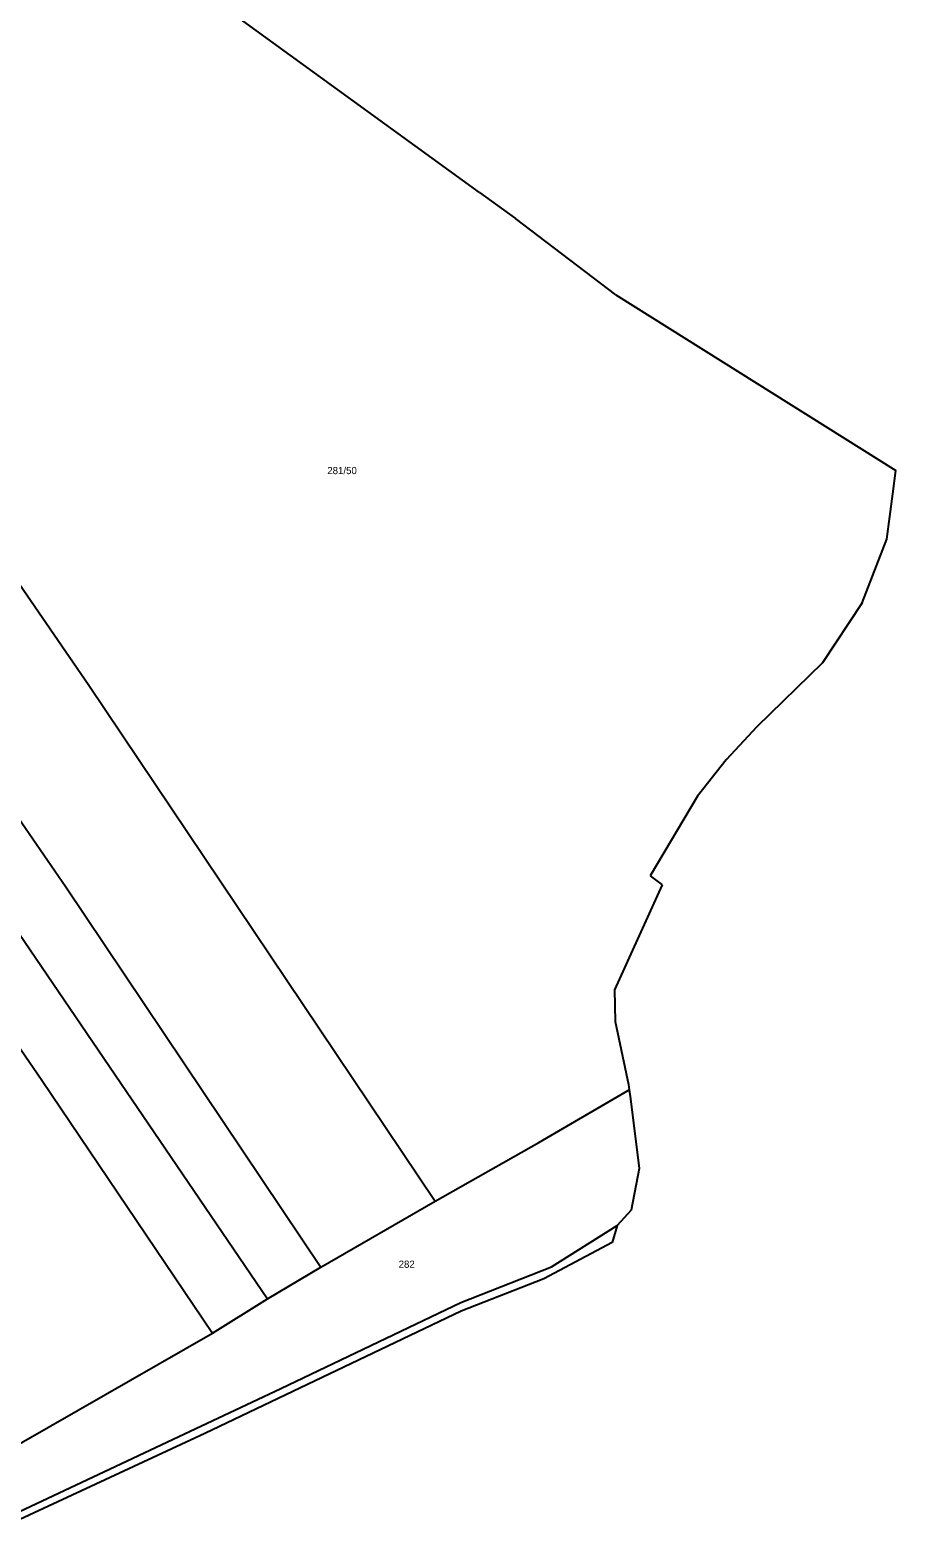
# Model space of a CAD drawing. Extents: x -779723 to -777378, y -1011169 to -1009297.
# Drawn here: x -777582.1 to -777378.3, y -1010780.6 to -1010425.5 of the extents above; entities that cross this region are included whole.
import ezdxf

# ---------------------------------------------------------------- set-up
doc = ezdxf.new("R2010")
doc.units = 0
doc.layers.add('KN_HRANICE', color=7, linetype='Continuous')
doc.layers.add('KN_PARCELY', color=7, linetype='Continuous')

msp = doc.modelspace()

# ---------------------------------------------------------------- linework, layer by layer
at = {"layer": 'KN_HRANICE'}
for p, q in [((-777476.3, -1010463.75), (-777554.28, -1010407.13)), ((-777673.1, -1010427.53), (-777568.32, -1010579.76)), ((-777476.3, -1010463.75), (-777467.85, -1010469.89)), ((-777444.27, -1010487.85), (-777467.85, -1010469.89)), ((-777444.27, -1010487.85), (-777378.31, -1010529.19)), ((-777379.04, -1010534.71), (-777378.31, -1010529.19)), ((-777637.27, -1010534.93), (-777573.74, -1010627.31)), ((-777380.45, -1010545.4), (-777379.04, -1010534.71)), ((-777386.25, -1010560.41), (-777380.45, -1010545.4)), ((-777386.25, -1010560.41), (-777395.6, -1010574.52)), ((-777653.97, -1010564.65), (-777579.37, -1010672.78)), ((-777395.6, -1010574.52), (-777411.07, -1010589.55)), ((-777568.32, -1010579.76), (-777486.74, -1010701.34)), ((-777411.07, -1010589.55), (-777418.22, -1010597.38)), ((-777418.22, -1010597.38), (-777425.01, -1010605.94)), ((-777425.01, -1010605.94), (-777436.13, -1010624.72)), ((-777601.48, -1010613.75), (-777526.23, -1010724.31)), ((-777436.13, -1010624.72), (-777433.29, -1010626.8)), ((-777573.74, -1010627.31), (-777513.72, -1010716.86)), ((-777433.29, -1010626.8), (-777444.54, -1010651.54)), ((-777444.54, -1010651.54), (-777444.36, -1010658.99)), ((-777444.36, -1010658.99), (-777441.24, -1010673.81)), ((-777579.37, -1010672.78), (-777539.17, -1010732.39)), ((-777441.24, -1010673.81), (-777441.08, -1010675.09)), ((-777462.35, -1010687.47), (-777441.08, -1010675.09)), ((-777441.08, -1010675.09), (-777440.81, -1010677.2)), ((-777440.81, -1010677.2), (-777438.71, -1010693.65)), ((-777486.74, -1010701.34), (-777462.35, -1010687.47)), ((-777438.71, -1010693.65), (-777440.66, -1010703.46)), ((-777513.72, -1010716.86), (-777486.74, -1010701.34)), ((-777440.66, -1010703.46), (-777443.92, -1010707.06)), ((-777459.4, -1010716.74), (-777443.92, -1010707.06)), ((-777443.92, -1010707.06), (-777445.06, -1010711.01)), ((-777445.06, -1010711.01), (-777461.16, -1010719.58)), ((-777526.23, -1010724.31), (-777513.72, -1010716.86)), ((-777480.75, -1010725.19), (-777459.4, -1010716.74)), ((-777461.16, -1010719.58), (-777480.67, -1010727.25)), ((-777539.17, -1010732.39), (-777526.23, -1010724.31)), ((-777480.67, -1010727.25), (-777541.04, -1010756.05)), ((-777523.08, -1010745.44), (-777480.75, -1010725.19)), ((-777593.25, -1010763.39), (-777539.17, -1010732.39)), ((-777597.11, -1010780.27), (-777523.08, -1010745.44)), ((-777541.04, -1010756.05), (-777593.97, -1010780.61))]:
    msp.add_line(p, q, dxfattribs=at)

# ---------------------------------------------------------------- texts
at = {"layer": 'KN_PARCELY'}
for s, p in [('281/50', (-777512.17, -1010530.07)), ('282', (-777495.37, -1010717.01))]:
    msp.add_text(s, height=1.7, dxfattribs=at).set_placement(p)

doc.saveas('drawing.dxf')
